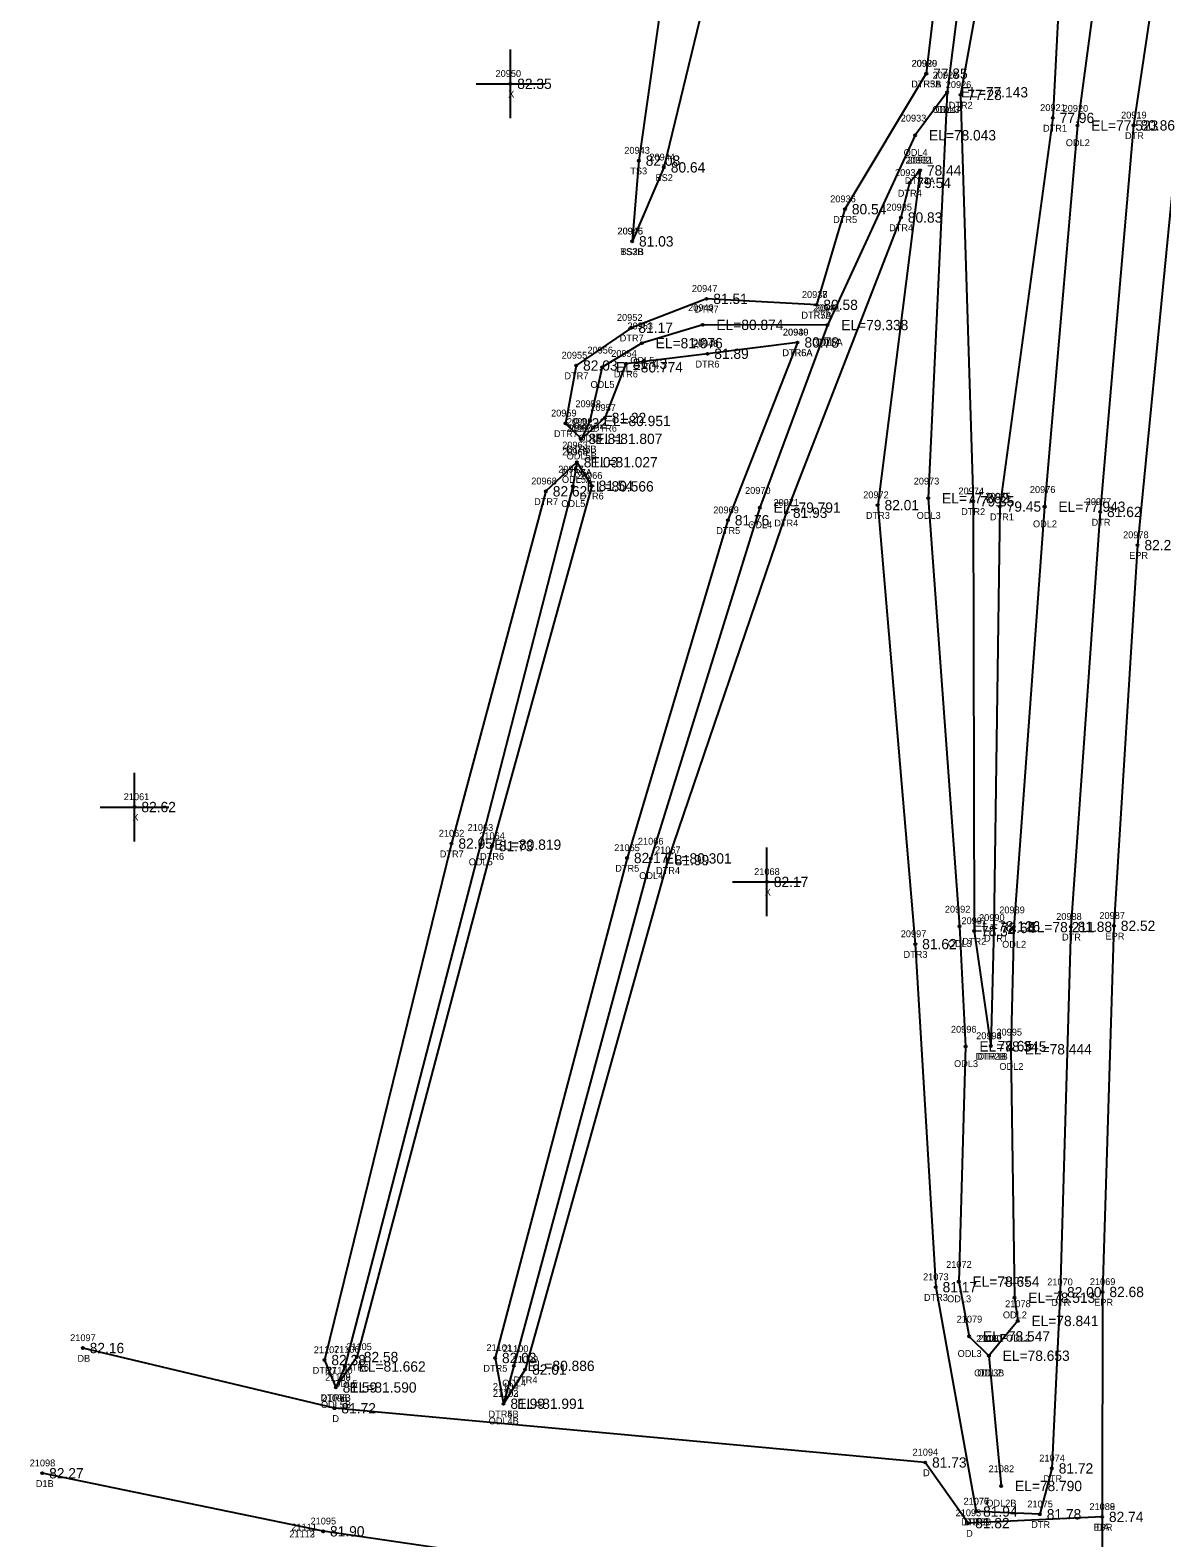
# Model space of a CAD drawing. Extents: x 2140110 to 2141565, y 506241 to 510327.
# Drawn here: x 2140403.7 to 2140568.4, y 507696.5 to 507916 of the extents above; entities that cross this region are included whole.
import ezdxf

# ---------------------------------------------------------------- set-up
doc = ezdxf.new("R2010")
doc.units = 0
for name, color, linetype in [('RD_DTM_BkLn2', 7, 'Continuous'), ('RD_DTM_BkLn_txCode', 7, 'Continuous'), ('RD_EX_Driveway', 7, 'Continuous'), ('RD_EX_Driveway_txCode', 7, 'Continuous'), ('RD_EX_H2O', 7, 'Continuous'), ('RD_EX_H2O_txCode', 7, 'Continuous'), ('RD_EX_Misc', 7, 'Continuous'), ('RD_EX_Misc_txCode', 7, 'Continuous'), ('RD_EX_Road', 7, 'Continuous'), ('RD_EX_Road_txCode', 7, 'Continuous'), ('RD_EX_TX_Driveway_ELEV', 7, 'Continuous'), ('RD_EX_TX_H2O_ELEV', 7, 'Continuous'), ('RD_EX_TX_Misc_ELEV', 7, 'Continuous'), ('RD_EX_TX_Road_ELEV', 7, 'Continuous'), ('RD_SMD_Locator', 7, 'Continuous')]:
    doc.layers.add(name, color=color, linetype=linetype)

msp = doc.modelspace()

# ---------------------------------------------------------------- linework, layer by layer
at = {"layer": 'RD_DTM_BkLn2'}
for points in [[(2140459.66, 508068.04), (2140496.18, 508060.84), (2140509.81, 508051.46), (2140533.98, 508049.48), (2140538.08, 508042.7), (2140542.56, 508045.34), (2140538.08, 508042.7), (2140526.61, 508035.38), (2140521.01, 508032.05), (2140525.34, 508022.05), (2140523.02, 508014.95), (2140516.43, 507980.43), (2140495.95, 507896.01), (2140491.32, 507885.24)], [(2140519.78, 508042.5), (2140512.87, 508033.11), (2140512.71, 508033.41), (2140513, 508019.95), (2140513.17, 508012.77), (2140504.28, 507981.33), (2140492.3, 507896.99), (2140491.32, 507885.24)]]:
    msp.add_lwpolyline(points, dxfattribs=at)
at = {"layer": 'RD_EX_Driveway'}
for points in [[(2140559.74, 507699.59), (2140540.26, 507698.69), (2140533.99, 507707.51), (2140447.99, 507715.4), (2140411.34, 507724.17)], [(2140559.81, 507681.93), (2140539.92, 507683.79), (2140446.33, 507697.49), (2140405.44, 507705.94)]]:
    msp.add_lwpolyline(points, dxfattribs=at)
at = {"layer": 'RD_EX_H2O'}
for points in [[(2140585.57, 508142.3), (2140592.14, 508133.08), (2140592.9, 508130.92), (2140589.17, 508103.98), (2140576.42, 508066.6), (2140561.47, 508016.3), (2140549.61, 507964.55), (2140539.12, 507906.56), (2140540.95, 507847.41), (2140541.11, 507784.86), (2140543.53, 507768.12)], [(2140588.29, 508137.13), (2140591.76, 508132.71), (2140592.18, 508131.48), (2140587.4, 508104.24), (2140573.58, 508068.11), (2140557.37, 508017.51), (2140544.39, 507963.64), (2140537.2, 507906.94), (2140534.44, 507847.85), (2140538.97, 507785.54), (2140539.88, 507768.06), (2140538.87, 507733.83), (2140540.4, 507725.87), (2140543.27, 507723.05)], [(2140587.07, 508134.31), (2140591.41, 508131.67), (2140584.38, 508105.23), (2140569.66, 508069.43), (2140554.12, 508016.78), (2140540.6, 507964.19), (2140534.15, 507909.65)], [(2140593.56, 508103.81), (2140601.24, 508101.05), (2140592.65, 508063.2), (2140581.57, 508013.96), (2140572.89, 507959.68), (2140564.34, 507902.12), (2140559.47, 507845.86), (2140555.18, 507785.48), (2140553.64, 507732.29), (2140552.43, 507706.65), (2140550.69, 507699.97), (2140541.42, 507700.37)], [(2140593.56, 508103.81), (2140583.89, 508064.25), (2140572.29, 508015.42), (2140564.21, 507962.24), (2140556.16, 507902.1), (2140551.38, 507846.62), (2140546.89, 507785.43), (2140546.48, 507767.65), (2140546.99, 507731.49), (2140547.46, 507728.11), (2140543.27, 507723.05), (2140545.06, 507704.09)], [(2140593.56, 508103.81), (2140591.16, 508103.79), (2140580.27, 508065.37), (2140567.36, 508016.47), (2140555.62, 507962.69), (2140552.57, 507903.21), (2140544.85, 507846.64), (2140543.99, 507785.31), (2140543.53, 507768.12)], [(2140534.15, 507909.65), (2140522.31, 507889.92), (2140518.16, 507876)], [(2140537.2, 507906.94), (2140532.54, 507900.68), (2140519.77, 507873.06), (2140509.92, 507846.49), (2140494.05, 507795.43), (2140474.09, 507721.57), (2140472.6, 507716.06)], [(2140533.24, 507895.57), (2140531.72, 507893.75), (2140530.46, 507888.72), (2140513.73, 507845.74), (2140496.52, 507795.17), (2140475.76, 507721.03), (2140472.6, 507716.06)], [(2140533.24, 507895.57), (2140527.07, 507846.85), (2140532.55, 507782.96), (2140535.52, 507733.03), (2140541.42, 507700.37)], [(2140518.16, 507876), (2140502.14, 507876.88), (2140491.23, 507872.67), (2140483.18, 507867.17), (2140481.64, 507858.75), (2140483.96, 507856.5)], [(2140519.77, 507873.06), (2140501.59, 507873.09), (2140492.75, 507870.43), (2140486.95, 507866.91), (2140485.17, 507859.1), (2140483.96, 507856.5)], [(2140515.41, 507870.53), (2140505.27, 507844.65), (2140490.58, 507795.49), (2140471.37, 507722.72), (2140472.6, 507716.06)], [(2140515.41, 507870.53), (2140502.28, 507868.88), (2140490.4, 507867.43), (2140487.35, 507859.54), (2140483.96, 507856.5)], [(2140483.28, 507853.09), (2140478.77, 507848.86), (2140465.03, 507797.59), (2140446.53, 507722.42), (2140448.17, 507718.43)], [(2140483.28, 507853.09), (2140485.43, 507849.67), (2140470.92, 507797.22), (2140451.25, 507722.86), (2140448.17, 507718.43)], [(2140483.28, 507853.09), (2140482.7, 507849.58), (2140469.23, 507797.43), (2140449.5, 507721.48), (2140448.17, 507718.43)]]:
    msp.add_lwpolyline(points, dxfattribs=at)
at = {"layer": 'RD_EX_Misc'}
for p, q in [((2140473.59, 507903.17), (2140473.59, 507913.17)), ((2140468.59, 507908.17), (2140478.59, 507908.17)), ((2140418.87, 507797.91), (2140418.87, 507807.91)), ((2140413.87, 507802.91), (2140423.87, 507802.91)), ((2140510.95, 507787.01), (2140510.95, 507797.01)), ((2140505.95, 507792.01), (2140515.95, 507792.01))]:
    msp.add_line(p, q, dxfattribs=at)
at = {"layer": 'RD_EX_Road'}
msp.add_lwpolyline([(2140681.68, 508333.39), (2140678, 508323.55), (2140662.26, 508279.8), (2140642.05, 508221.66), (2140625.62, 508169.11), (2140610.77, 508115.59), (2140598.26, 508062.62), (2140587.77, 508011.95), (2140578.4, 507958.88), (2140570.83, 507901.38), (2140564.91, 507841.03), (2140561.47, 507785.62), (2140559.81, 507732.33), (2140559.74, 507699.59), (2140559.81, 507681.93)], dxfattribs=at)
at = {"layer": 'RD_SMD_Locator'}
for centre in [(2140473.59, 507908.17), (2140534.15, 507909.65), (2140534.15, 507909.65), (2140537.2, 507906.94), (2140537.2, 507906.94), (2140539.12, 507906.56), (2140552.57, 507903.21), (2140556.16, 507902.1), (2140564.34, 507902.12), (2140532.54, 507900.68), (2140492.3, 507896.99), (2140495.95, 507896.01), (2140533.24, 507895.57), (2140533.24, 507895.57), (2140531.72, 507893.75), (2140522.31, 507889.92), (2140530.46, 507888.72), (2140491.32, 507885.24), (2140491.32, 507885.24), (2140502.14, 507876.88), (2140518.16, 507876), (2140518.16, 507876), (2140491.23, 507872.67), (2140501.59, 507873.09), (2140519.77, 507873.06), (2140519.77, 507873.06), (2140492.75, 507870.43), (2140515.41, 507870.53), (2140515.41, 507870.53), (2140502.28, 507868.88), (2140483.18, 507867.17), (2140486.95, 507866.91), (2140490.4, 507867.43), (2140487.35, 507859.54), (2140481.64, 507858.75), (2140485.17, 507859.1), (2140483.96, 507856.5), (2140483.96, 507856.5), (2140483.96, 507856.5), (2140483.28, 507853.09), (2140483.28, 507853.09), (2140483.28, 507853.09), (2140478.77, 507848.86), (2140482.7, 507849.58), (2140485.43, 507849.67), (2140509.92, 507846.49), (2140527.07, 507846.85), (2140534.44, 507847.85), (2140540.95, 507847.41), (2140544.85, 507846.64), (2140551.38, 507846.62), (2140505.27, 507844.65), (2140513.73, 507845.74), (2140559.47, 507845.86), (2140564.91, 507841.03), (2140418.87, 507802.91), (2140465.03, 507797.59), (2140469.23, 507797.43), (2140470.92, 507797.22), (2140490.58, 507795.49), (2140494.05, 507795.43), (2140496.52, 507795.17), (2140510.95, 507792.01), (2140538.97, 507785.54), (2140541.11, 507784.86), (2140543.99, 507785.31), (2140546.89, 507785.43), (2140555.18, 507785.48), (2140561.47, 507785.62), (2140532.55, 507782.96), (2140539.88, 507768.06), (2140543.53, 507768.12), (2140543.53, 507768.12), (2140546.48, 507767.65), (2140535.52, 507733.03), (2140538.87, 507733.83), (2140553.64, 507732.29), (2140559.81, 507732.33), (2140546.99, 507731.49), (2140547.46, 507728.11), (2140540.4, 507725.87), (2140411.34, 507724.17), (2140446.53, 507722.42), (2140449.5, 507721.48), (2140451.25, 507722.86), (2140471.37, 507722.72), (2140474.09, 507721.57), (2140543.27, 507723.05), (2140543.27, 507723.05), (2140475.76, 507721.03), (2140448.17, 507718.43), (2140448.17, 507718.43), (2140448.17, 507718.43), (2140447.99, 507715.4), (2140472.6, 507716.06), (2140472.6, 507716.06), (2140472.6, 507716.06), (2140405.44, 507705.94), (2140533.99, 507707.51), (2140552.43, 507706.65), (2140545.06, 507704.09), (2140541.42, 507700.37), (2140541.42, 507700.37), (2140550.69, 507699.97), (2140559.74, 507699.59), (2140559.74, 507699.59), (2140446.33, 507697.49), (2140540.26, 507698.69)]:
    msp.add_circle(centre, 0.15, dxfattribs=at)

# ---------------------------------------------------------------- texts
at = {"layer": 'RD_DTM_BkLn_txCode'}
for s, p in [('20943', (2140490.18, 507897.99)), ('20944', (2140493.83, 507897.01)), ('TS3', (2140491.05, 507894.99)), ('BS2', (2140494.72, 507894.01)), ('20946', (2140489.17, 507886.24)), ('20945', (2140489.2, 507886.24)), ('TS3B', (2140489.6, 507883.24)), ('BS2B', (2140489.62, 507883.24))]:
    msp.add_text(s, height=1, dxfattribs=at).set_placement(p)
at = {"layer": 'RD_EX_Driveway_txCode'}
for s, p in [('21097', (2140409.5, 507725.17)), ('DB', (2140410.56, 507722.17)), ('21096', (2140446.13, 507716.4)), ('D', (2140447.68, 507713.4)), ('21094', (2140532.15, 507708.51)), ('21098', (2140403.61, 507706.94)), ('D', (2140533.68, 507705.51)), ('D1B', (2140404.5, 507703.94)), ('21089', (2140557.9, 507700.59)), ('21095', (2140444.5, 507698.49)), ('21093', (2140538.42, 507699.69)), ('D', (2140539.95, 507696.69)), ('DA', (2140558.94, 507697.59))]:
    msp.add_text(s, height=1, dxfattribs=at).set_placement(p)
at = {"layer": 'RD_EX_H2O_txCode'}
for s, p in [('20930', (2140531.99, 507910.65)), ('20929', (2140532.03, 507910.65)), ('20927', (2140535.08, 507908.94)), ('20928', (2140535.08, 507908.94)), ('DTR5A', (2140531.94, 507907.65)), ('DTR3B', (2140531.96, 507907.65)), ('20926', (2140536.98, 507907.56)), ('DTR2', (2140537.41, 507904.56)), ('20933', (2140530.43, 507902.68)), ('ODL4A', (2140535.02, 507903.94)), ('ODL3', (2140535.51, 507903.94)), ('20921', (2140550.73, 507904.21)), ('20920', (2140554, 507904.1)), ('20919', (2140562.51, 507903.12)), ('DTR1', (2140551.14, 507901.21)), ('ODL2', (2140554.46, 507899.1)), ('DTR', (2140563.07, 507900.12)), ('ODL4', (2140530.85, 507897.68)), ('20932', (2140531.12, 507896.57)), ('20931', (2140531.4, 507896.57)), ('20934', (2140529.6, 507894.75)), ('DTR3A', (2140531.03, 507893.57)), ('DTR4', (2140530, 507891.75)), ('DTR4A', (2140531.03, 507893.57)), ('20936', (2140520.16, 507890.92)), ('20935', (2140528.34, 507889.72)), ('DTR5', (2140520.59, 507887.92)), ('DTR4', (2140528.74, 507886.72)), ('20947', (2140500.02, 507877.88)), ('20937', (2140516.04, 507877)), ('20938', (2140516.04, 507877)), ('20949', (2140499.47, 507875.09)), ('DTR7', (2140500.42, 507874.88)), ('DTR7A', (2140515.96, 507874)), ('DTR5B', (2140515.97, 507874)), ('20942', (2140517.65, 507875.06)), ('20941', (2140517.93, 507875.06)), ('20952', (2140489.11, 507873.67)), ('20953', (2140490.63, 507872.43)), ('DTR7', (2140489.51, 507870.67)), ('ODL5', (2140499.9, 507870.09)), ('20948', (2140500.17, 507869.88)), ('20940', (2140513.26, 507871.53)), ('20939', (2140513.29, 507871.53)), ('ODL5A', (2140517.59, 507870.06)), ('ODL4', (2140518.08, 507870.06)), ('20955', (2140481.06, 507868.17)), ('20956', (2140484.81, 507868.91)), ('20954', (2140488.28, 507868.43)), ('ODL5', (2140491.05, 507867.43)), ('DTR6A', (2140513.18, 507868.53)), ('DTR5A', (2140513.21, 507868.53)), ('DTR7', (2140481.46, 507865.17)), ('DTR6', (2140488.66, 507865.43)), ('DTR6', (2140500.54, 507866.88)), ('ODL5', (2140485.26, 507863.91)), ('20958', (2140483.06, 507861.1)), ('20959', (2140479.52, 507859.75)), ('20962', (2140481.82, 507858.5)), ('20957', (2140485.23, 507860.54)), ('DTR7', (2140479.93, 507856.75)), ('20960', (2140481.78, 507857.5)), ('20961', (2140482.1, 507857.5)), ('DTR6', (2140485.61, 507857.54)), ('20963', (2140481.14, 507855.09)), ('20964', (2140481.14, 507854.09)), ('20965', (2140481.14, 507854.09)), ('DTR6B', (2140481.75, 507854.5)), ('DTR7B', (2140481.77, 507854.5)), ('ODL5', (2140483.48, 507856.1)), ('ODL5B', (2140481.79, 507853.5)), ('20968', (2140476.63, 507849.86)), ('20967', (2140480.56, 507851.58)), ('DTR6A', (2140481.06, 507851.09)), ('ODL5A', (2140481.1, 507850.09)), ('DTR7A', (2140481.08, 507851.09)), ('20966', (2140483.27, 507850.67)), ('20973', (2140532.32, 507849.85)), ('DTR6', (2140483.69, 507847.67)), ('20970', (2140507.76, 507848.49)), ('20972', (2140524.96, 507847.85)), ('20974', (2140538.83, 507848.41)), ('20975', (2140542.73, 507847.64)), ('20976', (2140549.23, 507848.62)), ('DTR7', (2140477.05, 507846.86)), ('ODL5', (2140481.01, 507846.58)), ('20969', (2140503.13, 507845.65)), ('20971', (2140511.9, 507846.74)), ('DTR2', (2140539.23, 507845.41)), ('20977', (2140557.36, 507846.86)), ('ODL4', (2140508.23, 507843.49)), ('DTR4', (2140512.02, 507843.74)), ('DTR3', (2140525.36, 507844.85)), ('ODL3', (2140532.75, 507844.85)), ('DTR1', (2140543.42, 507844.64)), ('ODL2', (2140549.68, 507843.62)), ('DTR', (2140558.21, 507843.86)), ('DTR5', (2140503.56, 507842.65)), ('21063', (2140467.37, 507799.43)), ('21062', (2140463.17, 507798.59)), ('21064', (2140469.06, 507798.22)), ('21066', (2140492.16, 507797.43)), ('DTR7', (2140463.31, 507795.59)), ('DTR6', (2140469.18, 507795.22)), ('21065', (2140488.72, 507796.49)), ('21067', (2140494.66, 507796.17)), ('ODL5', (2140467.53, 507794.43)), ('DTR5', (2140488.86, 507793.49)), ('DTR4', (2140494.8, 507793.17)), ('ODL4', (2140492.35, 507792.43)), ('20992', (2140536.85, 507787.54)), ('20990', (2140541.83, 507786.31)), ('20989', (2140544.77, 507787.43)), ('20988', (2140553.06, 507786.48)), ('20997', (2140530.43, 507783.96)), ('20991', (2140539.27, 507785.86)), ('ODL3', (2140537.28, 507782.54)), ('DTR2', (2140539.39, 507782.86)), ('DTR1', (2140542.56, 507783.31)), ('ODL2', (2140545.19, 507782.43)), ('DTR', (2140553.91, 507783.48)), ('DTR3', (2140530.83, 507780.96)), ('20996', (2140537.74, 507770.06)), ('20993', (2140541.41, 507769.12)), ('20994', (2140541.41, 507769.12)), ('20995', (2140544.36, 507769.65)), ('ODL3', (2140538.19, 507765.06)), ('DTR2B', (2140541.34, 507766.12)), ('DTR1B', (2140541.62, 507766.12)), ('ODL2', (2140544.79, 507764.65)), ('21072', (2140537.04, 507735.83)), ('21073', (2140533.68, 507734.03)), ('21071', (2140545.44, 507733.49)), ('21070', (2140551.76, 507733.29)), ('DTR3', (2140533.8, 507731.03)), ('ODL3', (2140537.18, 507730.83)), ('21078', (2140545.63, 507730.11)), ('DTR', (2140552.37, 507730.29)), ('21079', (2140538.57, 507727.87)), ('ODL2', (2140545.3, 507728.49)), ('21080', (2140541.4, 507725.05)), ('21081', (2140541.72, 507725.05)), ('ODL2', (2140545.77, 507725.11)), ('21107', (2140444.97, 507723.42)), ('21106', (2140447.92, 507723.48)), ('21105', (2140449.7, 507723.86)), ('21101', (2140470.11, 507723.72)), ('21100', (2140472.5, 507723.57)), ('ODL3', (2140538.71, 507722.87)), ('DTR7', (2140444.81, 507720.42)), ('21110', (2140446.9, 507720.43)), ('DTR6', (2140449.51, 507720.86)), ('DTR5', (2140469.66, 507720.72)), ('21099', (2140473.92, 507722.03)), ('21108', (2140446.62, 507719.43)), ('21109', (2140446.62, 507719.43)), ('ODL5', (2140447.81, 507718.48)), ('21104', (2140471.05, 507718.06)), ('ODL4', (2140472.4, 507718.57)), ('DTR4', (2140474.04, 507719.03)), ('ODL3B', (2140541.11, 507720.05)), ('ODL2', (2140541.58, 507720.05)), ('DTR6B', (2140445.96, 507716.43)), ('DTR7B', (2140445.98, 507716.43)), ('21102', (2140471.05, 507717.06)), ('21103', (2140471.05, 507717.06)), ('ODL5B', (2140446.01, 507715.43)), ('DTR4B', (2140470.41, 507714.06)), ('DTR5B', (2140470.41, 507714.06)), ('ODL4B', (2140470.43, 507713.06)), ('21074', (2140550.6, 507707.65)), ('21082', (2140543.22, 507706.09)), ('DTR', (2140551.17, 507704.65)), ('21076', (2140539.56, 507701.37)), ('21077', (2140539.58, 507701.37)), ('ODL2B', (2140542.89, 507701.09)), ('21075', (2140548.86, 507700.97)), ('DTR3B', (2140539.23, 507698.37)), ('DTRB', (2140539.68, 507698.37)), ('21112', (2140441.41, 507696.6)), ('21113', (2140441.41, 507696.6)), ('21111', (2140441.7, 507697.6)), ('DTR', (2140549.42, 507697.97))]:
    msp.add_text(s, height=1, dxfattribs=at).set_placement(p)
at = {"layer": 'RD_EX_Misc_txCode'}
for s, p in [('20950', (2140471.43, 507909.17)), ('X', (2140473.27, 507906.17)), ('21061', (2140417.3, 507803.91)), ('X', (2140418.56, 507800.91)), ('21068', (2140509.09, 507793.01)), ('X', (2140510.63, 507790.01))]:
    msp.add_text(s, height=1, dxfattribs=at).set_placement(p)
at = {"layer": 'RD_EX_Road_txCode'}
for s, p in [('20978', (2140562.8, 507842.03)), ('EPR', (2140563.68, 507839.03)), ('20987', (2140559.35, 507786.62)), ('EPR', (2140560.24, 507783.62)), ('21069', (2140557.96, 507733.33)), ('EPR', (2140558.59, 507730.33)), ('21088', (2140557.9, 507700.59)), ('EPR', (2140558.51, 507697.59))]:
    msp.add_text(s, height=1, dxfattribs=at).set_placement(p)
at = {"layer": 'RD_EX_TX_Driveway_ELEV'}
for s, p in [('82.16', (2140412.34, 507723.42)), ('81.72', (2140448.99, 507714.65)), ('81.73', (2140534.99, 507706.76)), ('82.27', (2140406.44, 507705.19)), ('81.82', (2140541.26, 507697.94)), ('82.74', (2140560.74, 507698.84)), ('81.90', (2140447.33, 507696.74))]:
    msp.add_text(s, height=1.5, dxfattribs=at).set_placement(p)
at = {"layer": 'RD_EX_TX_H2O_ELEV'}
for s, p in [('77.85', (2140535.15, 507908.9)), ('77.85', (2140535.15, 507908.9)), ('EL=77.143', (2140539.2, 507906.19)), ('EL=77.143', (2140539.2, 507906.19)), ('77.28', (2140540.12, 507905.81)), ('77.96', (2140553.57, 507902.46)), ('EL=78.043', (2140534.54, 507899.93)), ('EL=77.523', (2140558.16, 507901.35)), ('80.86', (2140565.34, 507901.37)), ('78.44', (2140534.24, 507894.82)), ('78.44', (2140534.24, 507894.82)), ('79.54', (2140532.72, 507893)), ('80.54', (2140523.31, 507889.17)), ('80.83', (2140531.46, 507887.97)), ('81.51', (2140503.14, 507876.13)), ('80.58', (2140519.16, 507875.25)), ('80.58', (2140519.16, 507875.25)), ('81.17', (2140492.23, 507871.92)), ('EL=80.874', (2140503.59, 507872.34)), ('EL=79.338', (2140521.77, 507872.31)), ('EL=79.338', (2140521.77, 507872.31)), ('EL=81.076', (2140494.75, 507869.68)), ('80.78', (2140516.41, 507869.78)), ('80.78', (2140516.41, 507869.78)), ('81.89', (2140503.28, 507868.13)), ('82.03', (2140484.18, 507866.42)), ('EL=80.774', (2140488.95, 507866.16)), ('81.43', (2140491.4, 507866.68)), ('82.32', (2140482.64, 507858)), ('EL=80.951', (2140487.17, 507858.35)), ('81.22', (2140488.35, 507858.79)), ('81.81', (2140484.96, 507855.75)), ('81.81', (2140484.96, 507855.75)), ('EL=81.807', (2140485.96, 507855.75)), ('81.03', (2140484.28, 507852.34)), ('81.03', (2140484.28, 507852.34)), ('EL=81.027', (2140485.28, 507852.34)), ('82.62', (2140479.77, 507848.11)), ('EL=80.566', (2140484.7, 507848.83)), ('81.54', (2140486.43, 507848.92)), ('EL=77.862', (2140536.44, 507847.1)), ('EL=79.791', (2140511.92, 507845.74)), ('81.93', (2140514.73, 507844.99)), ('82.01', (2140528.07, 507846.1)), ('79.35', (2140541.95, 507846.66)), ('79.45', (2140545.85, 507845.89)), ('EL=77.943', (2140553.38, 507845.87)), ('81.62', (2140560.47, 507845.11)), ('81.76', (2140506.27, 507843.9)), ('82.95', (2140466.03, 507796.84)), ('EL=80.819', (2140471.23, 507796.68)), ('81.73', (2140471.92, 507796.47)), ('82.17', (2140491.58, 507794.74)), ('EL=80.301', (2140496.05, 507794.68)), ('81.99', (2140497.52, 507794.42)), ('EL=78.126', (2140540.97, 507784.79)), ('78.34', (2140542.11, 507784.11)), ('78.64', (2140544.99, 507784.56)), ('EL=78.211', (2140548.89, 507784.68)), ('81.88', (2140556.18, 507784.73)), ('81.62', (2140533.55, 507782.21)), ('EL=78.345', (2140541.88, 507767.31)), ('78.65', (2140544.53, 507767.37)), ('78.65', (2140544.53, 507767.37)), ('EL=78.444', (2140548.48, 507766.9)), ('EL=78.654', (2140540.87, 507733.08)), ('81.17', (2140536.52, 507732.28)), ('EL=78.513', (2140548.99, 507730.74)), ('82.00', (2140554.64, 507731.54)), ('EL=78.841', (2140549.46, 507727.36)), ('EL=78.547', (2140542.4, 507725.12)), ('82.58', (2140452.25, 507722.11)), ('82.03', (2140472.37, 507721.97)), ('EL=78.653', (2140545.27, 507722.3)), ('EL=78.653', (2140545.27, 507722.3)), ('82.38', (2140447.53, 507721.67)), ('EL=81.662', (2140451.5, 507720.73)), ('EL=80.886', (2140476.09, 507720.82)), ('82.01', (2140476.76, 507720.28)), ('81.59', (2140449.17, 507717.68)), ('81.59', (2140449.17, 507717.68)), ('EL=81.590', (2140450.17, 507717.68)), ('81.99', (2140473.6, 507715.31)), ('81.99', (2140473.6, 507715.31)), ('EL=81.991', (2140474.6, 507715.31)), ('81.72', (2140553.43, 507705.9)), ('EL=78.790', (2140547.06, 507703.34)), ('81.94', (2140542.42, 507699.62)), ('81.94', (2140542.42, 507699.62)), ('81.78', (2140551.69, 507699.22))]:
    msp.add_text(s, height=1.5, dxfattribs=at).set_placement(p)
at = {"layer": 'RD_EX_TX_Misc_ELEV'}
for s, p in [('82.35', (2140474.59, 507907.42)), ('82.08', (2140493.3, 507896.24)), ('80.64', (2140496.95, 507895.26)), ('81.03', (2140492.32, 507884.49)), ('81.03', (2140492.32, 507884.49)), ('82.62', (2140419.87, 507802.16)), ('82.17', (2140511.95, 507791.26))]:
    msp.add_text(s, height=1.5, dxfattribs=at).set_placement(p)
at = {"layer": 'RD_EX_TX_Road_ELEV'}
for s, p in [('82.24', (2140565.91, 507840.28)), ('82.52', (2140562.47, 507784.87)), ('82.68', (2140560.81, 507731.58)), ('82.74', (2140560.74, 507698.84))]:
    msp.add_text(s, height=1.5, dxfattribs=at).set_placement(p)

doc.saveas('drawing.dxf')
